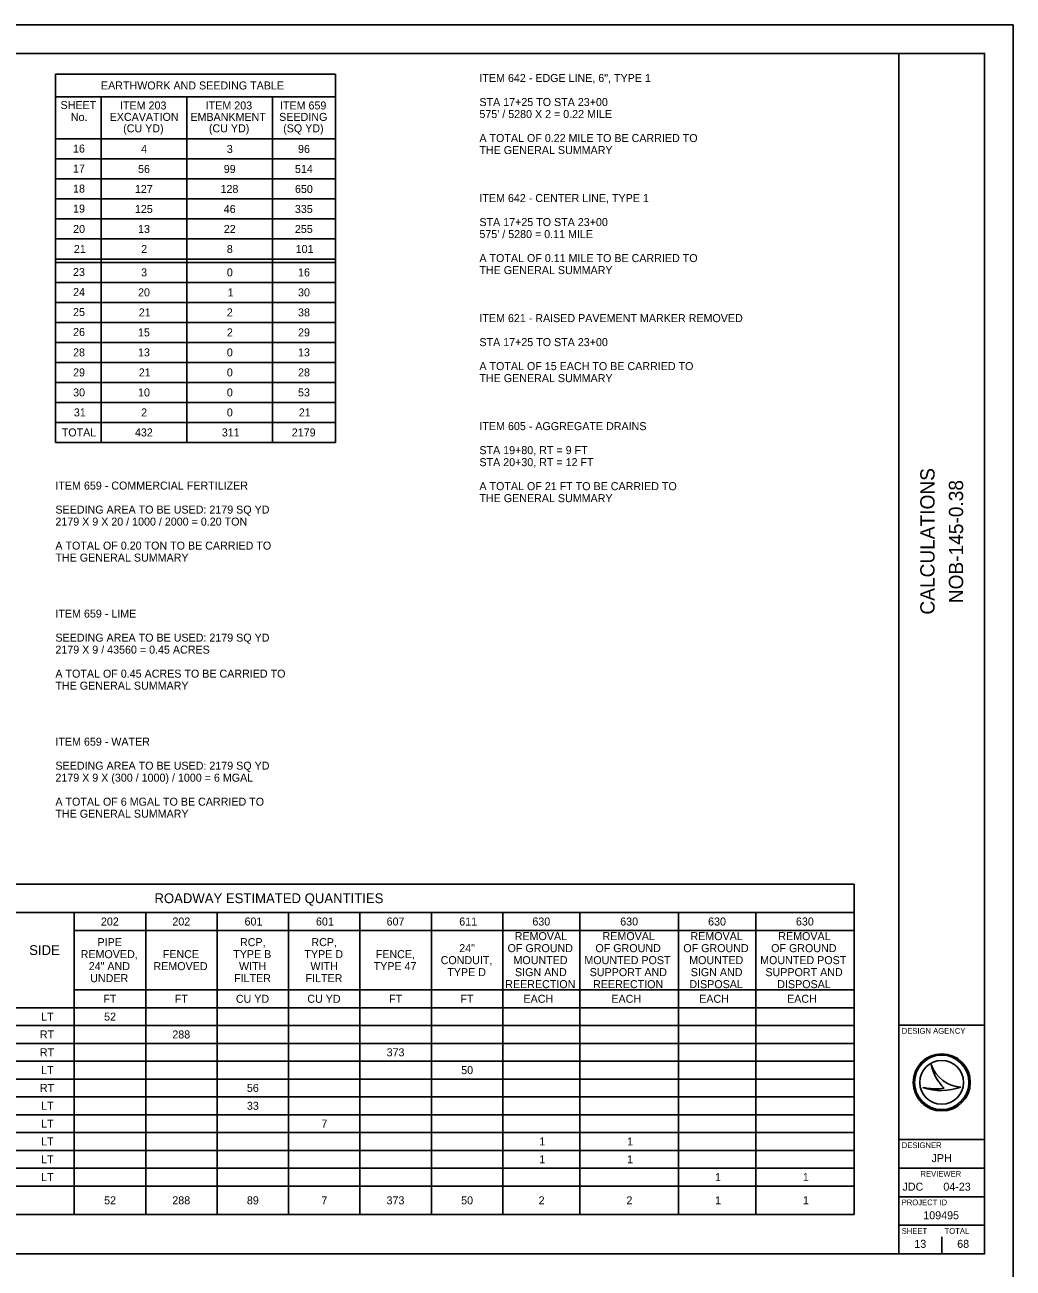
# Model space of a CAD drawing. Extents: x 0 to 34, y -22 to 22.
# Drawn here: x 16.71 to 34, y 0.25 to 22 of the extents above; entities that cross this region are included whole.
import ezdxf

# ---------------------------------------------------------------- set-up
doc = ezdxf.new("R2010")
doc.units = 0
for name, color, linetype in [('SH_Border', 7, 'Continuous'), ('SH_Cut_Line', 7, 'Continuous'), ('SH_Data', 7, 'Continuous'), ('TX_P_1', 7, 'Continuous'), ('TX_P_20', 7, 'Continuous')]:
    doc.layers.add(name, color=color, linetype=linetype)

msp = doc.modelspace()

# ---------------------------------------------------------------- linework, layer by layer
at = {"layer": 'SH_Border'}
for p, q in [((32, 0.5), (32, 21.5)), ((32, 4.5), (33.5, 4.5)), ((32, 2.5), (33.5, 2.5)), ((32, 2), (33.5, 2)), ((32, 1.5), (33.5, 1.5)), ((32, 1), (33.5, 1))]:
    msp.add_line(p, q, dxfattribs=at)
msp.add_lwpolyline([(1.5, 21.5), (33.5, 21.5), (33.5, 0.5), (1.5, 0.5)], close=True, dxfattribs=at)
at = {"layer": 'SH_Cut_Line'}
msp.add_lwpolyline([(0, 0), (34, 0), (34, 22), (0, 22)], close=True, dxfattribs=at)
at = {"layer": 'SH_Data'}
for p, q in [((31.22, 6.97), (12.119, 6.97)), ((31.22, 1.186), (31.22, 6.97)), ((31.22, 6.47), (12.119, 6.47)), ((17.57, 1.186), (17.57, 6.47)), ((18.82, 1.186), (18.82, 6.47)), ((20.07, 1.186), (20.07, 6.47)), ((21.32, 1.186), (21.32, 6.47)), ((22.57, 1.186), (22.57, 6.47)), ((23.82, 1.186), (23.82, 6.47)), ((25.07, 1.186), (25.07, 6.47)), ((26.42, 1.186), (26.42, 6.47)), ((28.145, 1.186), (28.145, 6.47)), ((29.495, 1.186), (29.495, 6.47)), ((31.22, 6.158), (17.57, 6.158)), ((31.22, 5.118), (17.57, 5.118)), ((31.22, 4.806), (12.119, 4.806)), ((31.22, 4.494), (12.119, 4.494)), ((31.22, 4.182), (12.119, 4.182)), ((31.22, 3.87), (12.119, 3.87)), ((32.567, 3.81), (32.567, 3.81)), ((31.22, 3.558), (12.119, 3.558)), ((32.75, 3.5), (32.75, 3.5)), ((32.417, 3.41), (32.417, 3.41)), ((33.087, 3.419), (33.087, 3.419)), ((31.22, 3.246), (12.119, 3.246)), ((31.22, 2.934), (12.119, 2.934)), ((31.22, 2.622), (12.119, 2.622)), ((31.22, 2.31), (12.119, 2.31)), ((31.22, 1.998), (12.119, 1.998)), ((31.22, 1.686), (12.119, 1.686)), ((31.22, 1.686), (12.119, 1.686)), ((31.22, 1.186), (12.119, 1.186)), ((32.375, 0.675), (32.375, 0.675)), ((32.75, 0.5), (32.75, 0.8))]:
    msp.add_line(p, q, dxfattribs=at)
for radius in [0.5, 0.477, 0.477, 0.382]:
    msp.add_circle((32.75, 3.5), radius, dxfattribs=at)
for centre, radius, start, end in [((33.116, 3.998), 0.58, 198.9257, 198.9319), ((33.347, 3.97), 0.796, 191.6379, 191.6421), ((33.116, 3.998), 0.58, 198.9319, 267.1657), ((33.347, 3.97), 0.796, 191.6421, 226.0947), ((32.739, 4.37), 1.013, 251.4576, 290.0832), ((32.648, 4.654), 1.266, 259.4964, 259.4995), ((32.739, 4.37), 1.013, 251.4527, 251.4576), ((32.648, 4.654), 1.266, 259.4995, 276.6672)]:
    msp.add_arc(centre, radius, start, end, dxfattribs=at)
at = {"layer": 'TX_P_1'}
for p, q in [((22.14, 21.14), (17.24, 21.14)), ((17.24, 21.14), (17.24, 14.695)), ((22.14, 21.14), (22.14, 14.695)), ((22.14, 20.74), (17.24, 20.74)), ((18.04, 20.74), (18.04, 14.695)), ((19.54, 20.74), (19.54, 14.695)), ((21.04, 20.74), (21.04, 14.695)), ((22.14, 20.004), (17.24, 20.004)), ((22.14, 19.654), (17.24, 19.654)), ((22.14, 19.304), (17.24, 19.304)), ((22.14, 18.954), (17.24, 18.954)), ((22.14, 18.604), (17.24, 18.604)), ((22.14, 18.604), (17.24, 18.604)), ((22.14, 18.254), (17.24, 18.254)), ((22.14, 17.904), (17.24, 17.904)), ((22.14, 17.845), (17.24, 17.845)), ((22.14, 17.495), (17.24, 17.495)), ((22.14, 17.145), (17.24, 17.145)), ((22.14, 16.795), (17.24, 16.795)), ((22.14, 16.445), (17.24, 16.445)), ((22.14, 16.445), (17.24, 16.445)), ((22.14, 16.095), (17.24, 16.095)), ((22.14, 15.745), (17.24, 15.745)), ((22.14, 15.395), (17.24, 15.395)), ((22.14, 15.045), (17.24, 15.045)), ((22.14, 14.695), (17.24, 14.695))]:
    msp.add_line(p, q, dxfattribs=at)

# ---------------------------------------------------------------- texts
at = {"layer": 'SH_Data'}
for s, p in [('CALCULATIONS', (32.625, 11.683)), ('NOB-145-0.38', (33.125, 11.882))]:
    msp.add_text(s, height=0.25, rotation=90, dxfattribs=at).set_placement(p)
for s, height, p in [('ROADWAY ESTIMATED QUANTITIES', 0.17175, (18.973, 6.635)), ('SIDE', 0.1717, (16.781, 5.728)), ('DESIGN AGENCY', 0.1, (32.05, 4.35)), ('DESIGNER', 0.1, (32.05, 2.35)), ('JPH', 0.14, (32.573, 2.105)), ('JDC', 0.14, (32.064, 1.605)), ('REVIEWER', 0.1, (32.378, 1.85)), ('04-23', 0.14, (32.779, 1.605)), ('PROJECT ID', 0.1, (32.05, 1.35)), ('109495', 0.14, (32.428, 1.105)), ('SHEET', 0.1, (32.05, 0.85)), ('TOTAL', 0.1, (32.8, 0.85)), ('13', 0.14, (32.271, 0.605)), ('68', 0.14, (33.021, 0.605))]:
    msp.add_text(s, height=height, dxfattribs=at).set_placement(p)
at = {"layer": 'TX_P_1'}
for s, p in [('ITEM 642 - EDGE LINE, 6", TYPE 1', (24.66, 21)), ('EARTHWORK AND SEEDING TABLE', (18.037, 20.87)), ('SHEET', (17.33, 20.527)), ('STA 17+25 TO STA 23+00', (24.66, 20.58)), ('No.', (17.51, 20.317)), ('EXCAVATION', (18.189, 20.32)), ('ITEM 203', (18.371, 20.52)), ('EMBANKMENT', (19.602, 20.32)), ('ITEM 203', (19.871, 20.52)), ('SEEDING', (21.156, 20.32)), ('ITEM 659', (21.17, 20.52)), ("575' / 5280 X 2 = 0.22 MILE", (24.66, 20.37)), ('(CU YD)', (18.426, 20.12)), ('(CU YD)', (19.926, 20.12)), ('(SQ YD)', (21.226, 20.12)), ('A TOTAL OF 0.22 MILE TO BE CARRIED TO', (24.66, 19.95)), ('16', (17.548, 19.766)), ('4', (18.74, 19.759)), ('3', (20.24, 19.759)), ('96', (21.486, 19.759)), ('THE GENERAL SUMMARY', (24.66, 19.74)), ('17', (17.548, 19.416)), ('56', (18.686, 19.409)), ('99', (20.186, 19.409)), ('514', (21.432, 19.409)), ('18', (17.549, 19.066)), ('127', (18.631, 19.059)), ('128', (20.13, 19.059)), ('650', (21.432, 19.059)), ('ITEM 642 - CENTER LINE, TYPE 1', (24.66, 18.9)), ('19', (17.549, 18.716)), ('125', (18.631, 18.709)), ('46', (20.186, 18.709)), ('335', (21.431, 18.709)), ('20', (17.55, 18.359)), ('13', (18.686, 18.359)), ('22', (20.186, 18.359)), ('255', (21.431, 18.359)), ('STA 17+25 TO STA 23+00', (24.66, 18.48)), ("575' / 5280 = 0.11 MILE", (24.66, 18.27)), ('21', (17.563, 18.009)), ('2', (18.741, 18.009)), ('8', (20.24, 18.009)), ('101', (21.445, 18.009)), ('A TOTAL OF 0.11 MILE TO BE CARRIED TO', (24.66, 17.85)), ('23', (17.548, 17.606)), ('3', (18.74, 17.6)), ('0', (20.24, 17.6)), ('16', (21.486, 17.6)), ('THE GENERAL SUMMARY', (24.66, 17.64)), ('24', (17.549, 17.256)), ('20', (18.686, 17.25)), ('1', (20.254, 17.25)), ('30', (21.486, 17.25)), ('25', (17.549, 16.906)), ('21', (18.699, 16.9)), ('2', (20.24, 16.9)), ('38', (21.486, 16.9)), ('ITEM 621 - RAISED PAVEMENT MARKER REMOVED', (24.66, 16.8)), ('26', (17.549, 16.556)), ('15', (18.685, 16.55)), ('2', (20.241, 16.55)), ('29', (21.486, 16.55)), ('28', (17.549, 16.2)), ('13', (18.686, 16.2)), ('0', (20.24, 16.2)), ('13', (21.486, 16.2)), ('STA 17+25 TO STA 23+00', (24.66, 16.38)), ('A TOTAL OF 15 EACH TO BE CARRIED TO', (24.66, 15.96)), ('29', (17.549, 15.85)), ('21', (18.699, 15.85)), ('0', (20.24, 15.85)), ('28', (21.486, 15.85)), ('THE GENERAL SUMMARY', (24.66, 15.75)), ('30', (17.55, 15.5)), ('10', (18.686, 15.5)), ('0', (20.24, 15.5)), ('53', (21.486, 15.5)), ('31', (17.563, 15.15)), ('2', (18.741, 15.15)), ('0', (20.24, 15.15)), ('21', (21.499, 15.15)), ('ITEM 605 - AGGREGATE DRAINS', (24.66, 14.91)), ('TOTAL', (17.351, 14.8)), ('432', (18.632, 14.8)), ('311', (20.152, 14.8)), ('2179', (21.377, 14.8)), ('STA 19+80, RT = 9 FT', (24.66, 14.49)), ('STA 20+30, RT = 12 FT', (24.66, 14.28)), ('ITEM 659 - COMMERCIAL FERTILIZER', (17.24, 13.87)), ('A TOTAL OF 21 FT TO BE CARRIED TO', (24.66, 13.86)), ('THE GENERAL SUMMARY', (24.66, 13.65)), ('SEEDING AREA TO BE USED: 2179 SQ YD', (17.24, 13.45)), ('2179 X 9 X 20 / 1000 / 2000 = 0.20 TON', (17.24, 13.24)), ('A TOTAL OF 0.20 TON TO BE CARRIED TO', (17.24, 12.82)), ('THE GENERAL SUMMARY', (17.24, 12.61)), ('ITEM 659 - LIME', (17.24, 11.63)), ('SEEDING AREA TO BE USED: 2179 SQ YD', (17.24, 11.21)), ('2179 X 9 / 43560 = 0.45 ACRES', (17.24, 11)), ('A TOTAL OF 0.45 ACRES TO BE CARRIED TO', (17.24, 10.58)), ('THE GENERAL SUMMARY', (17.24, 10.37)), ('ITEM 659 - WATER', (17.24, 9.39)), ('SEEDING AREA TO BE USED: 2179 SQ YD', (17.24, 8.97)), ('2179 X 9 X (300 / 1000) / 1000 = 6 MGAL', (17.24, 8.76)), ('A TOTAL OF 6 MGAL TO BE CARRIED TO', (17.24, 8.34)), ('THE GENERAL SUMMARY', (17.24, 8.13))]:
    msp.add_text(s, height=0.14, dxfattribs=at).set_placement(p)
at = {"layer": 'TX_P_20'}
for s, p in [('202', (18.037, 6.244)), ('202', (19.287, 6.244)), ('601', (20.55, 6.244)), ('601', (21.8, 6.244)), ('607', (23.036, 6.244)), ('611', (24.307, 6.244)), ('630', (25.587, 6.244)), ('630', (27.124, 6.244)), ('630', (28.662, 6.244)), ('630', (30.199, 6.244)), ('REMOVAL', (25.278, 5.988)), ('REMOVAL', (26.815, 5.988)), ('REMOVAL', (28.353, 5.988)), ('REMOVAL', (29.89, 5.988)), ('PIPE', (17.977, 5.883)), ('RCP,', (20.47, 5.883)), ('RCP,', (21.72, 5.883)), ('24"', (24.307, 5.778)), ('OF GROUND', (25.153, 5.778)), ('OF GROUND', (26.69, 5.778)), ('OF GROUND', (28.228, 5.778)), ('OF GROUND', (29.765, 5.778)), ('REMOVED,', (17.682, 5.673)), ('FENCE', (19.119, 5.673)), ('TYPE B', (20.352, 5.673)), ('TYPE D', (21.597, 5.673)), ('FENCE,', (22.846, 5.673)), ('CONDUIT,', (23.982, 5.568)), ('MOUNTED', (25.256, 5.568)), ('MOUNTED POST', (26.497, 5.568)), ('MOUNTED', (28.331, 5.568)), ('MOUNTED POST', (29.572, 5.568)), ('24" AND', (17.823, 5.463)), ('REMOVED', (18.956, 5.463)), ('WITH', (20.453, 5.463)), ('WITH', (21.703, 5.463)), ('TYPE 47', (22.809, 5.463)), ('TYPE D', (24.098, 5.358)), ('SIGN AND', (25.283, 5.358)), ('SUPPORT AND', (26.59, 5.358)), ('SIGN AND', (28.358, 5.358)), ('SUPPORT AND', (29.665, 5.358)), ('UNDER', (17.849, 5.253)), ('FILTER', (20.367, 5.253)), ('FILTER', (21.617, 5.253)), ('REERECTION', (25.112, 5.148)), ('REERECTION', (26.649, 5.148)), ('DISPOSAL', (28.334, 5.148)), ('DISPOSAL', (29.872, 5.148)), ('FT', (18.078, 4.892)), ('FT', (19.328, 4.892)), ('CU YD', (20.398, 4.892)), ('CU YD', (21.648, 4.892)), ('FT', (23.079, 4.892)), ('FT', (24.329, 4.892)), ('EACH', (25.431, 4.892)), ('EACH', (26.969, 4.892)), ('EACH', (28.506, 4.892)), ('EACH', (30.044, 4.892)), ('LT', (16.99, 4.58)), ('52', (18.092, 4.58)), ('RT', (16.968, 4.268)), ('288', (19.286, 4.268)), ('RT', (16.968, 3.956)), ('373', (23.036, 3.956)), ('LT', (16.99, 3.644)), ('50', (24.341, 3.644)), ('RT', (16.968, 3.332)), ('56', (20.591, 3.332)), ('LT', (16.99, 3.02)), ('33', (20.591, 3.02)), ('LT', (16.99, 2.708)), ('7', (21.895, 2.708)), ('LT', (16.99, 2.396)), ('1', (25.708, 2.396)), ('1', (27.245, 2.396)), ('LT', (16.99, 2.084)), ('1', (25.708, 2.084)), ('1', (27.245, 2.084)), ('LT', (16.99, 1.772)), ('1', (28.783, 1.772)), ('1', (30.32, 1.772)), ('52', (18.092, 1.366)), ('288', (19.286, 1.366)), ('89', (20.591, 1.366)), ('7', (21.895, 1.366)), ('373', (23.035, 1.366)), ('50', (24.34, 1.366)), ('2', (25.696, 1.366)), ('2', (27.233, 1.366)), ('1', (28.784, 1.366)), ('1', (30.321, 1.366))]:
    msp.add_text(s, height=0.14, dxfattribs=at).set_placement(p)

doc.saveas('drawing.dxf')
